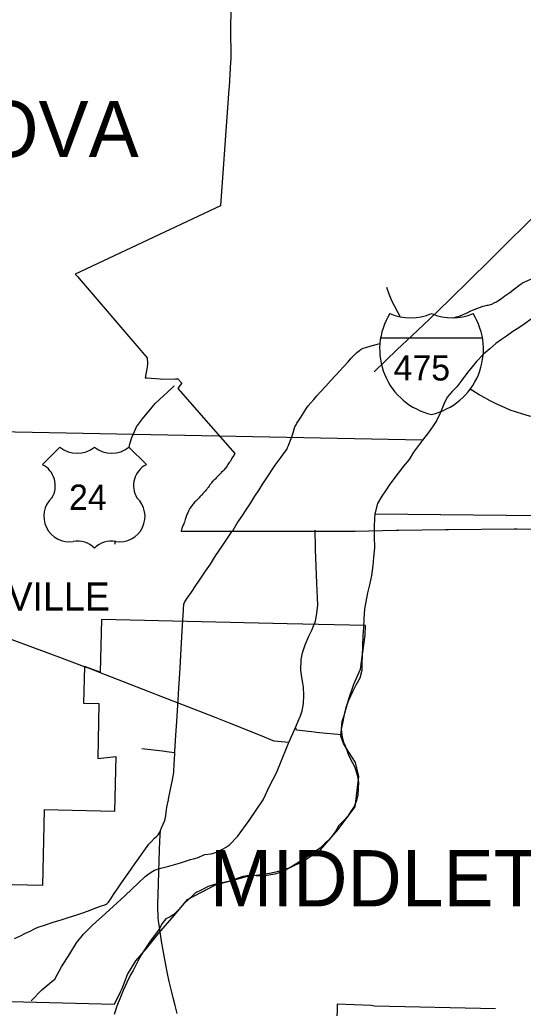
# Model space of a CAD drawing. Extents: x -232 to 448, y 619 to 1059.
# Drawn here: x 113.08 to 131.46, y 864.09 to 900.18 of the extents above; entities that cross this region are included whole.
import ezdxf

# ---------------------------------------------------------------- set-up
doc = ezdxf.new("R2010")
doc.units = 0
doc.layers.add('Default', color=7, linetype='Continuous')

msp = doc.modelspace()

# ---------------------------------------------------------------- linework, layer by layer
at = {"layer": 'Default'}
for p, q in [((126.25, 888.562), (129.971, 888.562)), ((114.542, 884.571), (113.908, 883.937)), ((114.542, 884.571), (113.908, 883.937)), ((117.698, 883.937), (117.063, 884.571)), ((117.698, 883.937), (117.063, 884.571)), ((116.063, 878.283), (116.016, 876.357)), ((115.437, 876.567), (115.405, 875.233)), ((115.405, 875.233), (115.969, 875.22)), ((115.969, 875.22), (115.921, 873.207)), ((116.583, 873.285), (116.535, 871.272)), ((113.97, 871.334), (113.904, 868.564)), ((116.535, 871.272), (113.97, 871.334)), ((113.904, 868.564), (111.904, 868.613)), ((112.16, 864.343), (116.541, 864.237))]:
    msp.add_line(p, q, dxfattribs=at)
for points in [[(120.796, 900.784), (120.793, 900.72), (120.769, 900.023), (120.77, 899.926), (120.779, 898.736), (120.774, 898.651), (120.716, 897.732), (120.711, 897.665), (120.406, 893.385)], [(129.536, 890.712), (129.559, 890.735), (130.184, 891.346), (130.828, 891.986), (131.61, 892.767), (132.138, 893.272), (132.641, 893.676), (132.77, 893.765)], [(120.406, 893.385), (115.098, 890.889)], [(127.784, 884.833), (111.649, 885.151), (111.657, 885.999), (110.121, 886.009), (110.165, 888.733), (104.807, 888.708), (99.321, 888.696), (99.344, 891.498)], [(131.422, 890.565), (131.436, 890.575), (131.52, 890.612), (131.739, 890.714), (131.945, 890.809), (132.197, 890.926), (132.43, 891.036), (132.65, 891.135), (132.869, 891.238), (132.922, 891.262)], [(115.098, 890.889), (115.191, 890.792), (115.242, 890.734), (117.5, 888.103), (117.558, 888.034), (117.723, 887.839), (117.73, 887.783), (117.742, 887.679), (117.739, 887.609), (117.734, 887.504), (117.721, 887.438), (117.657, 887.113)], [(127.389, 888.643), (128.034, 889.251), (128.765, 889.956), (129.536, 890.712)], [(130.822, 890.125), (130.964, 890.227), (131.136, 890.358), (131.293, 890.476), (131.386, 890.541), (131.422, 890.565)], [(126.971, 889.346), (126.897, 889.48), (126.768, 889.716), (126.664, 889.921), (126.563, 890.164), (126.476, 890.408)], [(130.518, 889.906), (130.574, 889.939), (130.665, 890.005), (130.792, 890.104), (130.822, 890.125)], [(128.905, 889.301), (128.951, 889.313), (129.077, 889.348), (129.151, 889.372), (129.239, 889.407), (129.355, 889.461), (129.435, 889.497), (129.505, 889.537), (129.586, 889.572), (129.73, 889.626), (129.899, 889.689), (129.985, 889.72), (130.061, 889.742), (130.148, 889.761), (130.173, 889.766)], [(130.173, 889.766), (130.23, 889.778), (130.31, 889.803), (130.401, 889.845), (130.485, 889.887), (130.518, 889.906)], [(132.003, 889.452), (131.763, 889.258), (131.532, 889.094), (131.294, 888.934), (131.075, 888.795), (130.843, 888.627), (130.67, 888.513), (130.463, 888.357), (130.235, 888.169), (130.011, 887.966), (129.749, 887.701), (129.589, 887.51), (129.421, 887.298), (129.214, 887.02), (129.029, 886.784), (128.863, 886.611), (128.698, 886.413), (128.589, 886.207), (128.441, 885.838), (128.292, 885.539), (128.169, 885.352), (128.006, 885.117), (127.784, 884.833)], [(126.016, 887.329), (126.854, 888.139), (127.389, 888.643)], [(120.835, 881.505), (120.865, 881.55), (121.017, 881.796), (121.186, 882.042), (121.346, 882.286), (121.512, 882.544), (121.663, 882.782), (121.812, 883.023), (121.929, 883.198), (122.047, 883.379), (122.175, 883.566), (122.301, 883.773), (122.351, 883.846), (122.399, 883.916), (122.473, 884.015), (122.617, 884.21), (122.738, 884.377), (122.824, 884.495), (122.858, 884.56), (122.894, 884.641), (122.937, 884.772), (122.988, 884.893), (123.024, 884.985), (123.057, 885.105), (123.098, 885.23), (123.124, 885.312), (123.166, 885.394), (123.198, 885.457), (123.252, 885.536), (123.323, 885.646), (123.449, 885.843), (123.55, 886.004), (123.605, 886.083), (123.699, 886.193), (123.811, 886.318), (123.922, 886.444), (124.055, 886.59), (124.249, 886.809), (124.43, 887.005), (124.603, 887.196), (124.757, 887.362), (124.894, 887.514), (125.063, 887.696), (125.178, 887.82), (125.294, 887.945), (125.386, 888.034), (125.475, 888.107), (125.541, 888.151), (125.615, 888.187), (125.712, 888.22), (125.901, 888.273), (126.144, 888.339), (126.224, 888.359)], [(117.657, 887.113), (117.716, 887.111), (118.201, 887.07), (118.271, 887.064), (118.761, 887.066), (118.842, 887.066), (118.982, 886.929), (118.996, 886.916), (118.925, 886.823), (118.842, 886.713), (120.05, 885.34), (120.923, 884.343)], [(117.072, 884.562), (117.1, 884.694), (117.173, 884.933), (117.267, 885.151), (117.334, 885.314), (117.552, 885.606), (117.91, 886.04), (118.015, 886.171), (118.629, 886.73), (118.714, 886.812)], [(129.893, 886.46), (129.856, 886.481), (129.617, 886.627), (129.519, 886.689)], [(133.976, 885.384), (133.832, 885.388), (133.533, 885.407), (133.249, 885.428), (133.012, 885.452), (132.773, 885.485), (132.549, 885.521), (132.322, 885.564), (132.13, 885.604), (131.914, 885.653), (131.694, 885.712), (131.449, 885.779), (131.219, 885.853), (130.987, 885.93), (130.802, 886.007), (130.601, 886.099), (130.422, 886.178), (130.247, 886.263), (130.053, 886.371), (129.893, 886.46)], [(127.784, 884.833), (127.454, 884.395), (127.289, 884.127), (127.091, 883.881), (126.894, 883.632), (126.589, 883.222), (126.433, 882.987), (126.297, 882.785), (126.142, 882.518), (126.046, 882.137)], [(120.923, 884.343), (120.893, 884.286), (120.876, 884.257), (120.859, 884.222), (120.821, 884.176), (120.793, 884.117), (120.765, 884.069), (120.722, 884.012), (120.698, 883.98), (120.673, 883.94), (120.646, 883.892), (120.617, 883.848), (120.592, 883.808), (120.566, 883.779), (120.536, 883.746), (120.494, 883.704), (120.445, 883.659), (120.429, 883.632), (120.391, 883.601), (120.361, 883.567), (120.342, 883.544), (120.307, 883.519), (120.276, 883.486), (120.246, 883.456), (120.219, 883.416), (120.199, 883.399), (120.165, 883.374), (120.144, 883.344), (120.102, 883.309), (120.082, 883.275), (120.063, 883.251), (120.034, 883.209), (120.005, 883.183), (119.986, 883.151), (119.964, 883.117), (119.935, 883.083), (119.915, 883.05), (119.883, 883.02), (119.843, 882.968)], [(119.843, 882.968), (119.794, 882.916), (119.764, 882.882), (119.749, 882.85), (119.723, 882.828), (119.687, 882.795), (119.647, 882.759), (119.632, 882.73), (119.605, 882.706), (119.558, 882.652), (119.532, 882.634), (119.503, 882.604), (119.472, 882.578), (119.424, 882.521), (119.38, 882.473), (119.361, 882.432), (119.336, 882.404), (119.3, 882.35), (119.265, 882.307), (119.25, 882.266), (119.236, 882.237), (119.207, 882.174), (119.189, 882.143), (119.179, 882.112), (119.152, 882.041), (119.14, 882.009), (119.131, 881.966), (119.119, 881.935), (119.106, 881.887), (119.088, 881.837), (119.075, 881.808), (119.062, 881.77), (119.048, 881.741), (119.033, 881.705), (119.009, 881.644), (118.995, 881.607), (118.982, 881.561), (118.971, 881.527), (118.967, 881.51)], [(126.046, 882.137), (126.025, 881.968), (126.019, 881.673), (126.011, 881.309), (126.024, 880.894), (125.994, 880.55), (125.972, 880.259), (125.914, 879.895), (125.84, 879.546), (125.771, 879.251), (125.716, 878.932), (125.668, 878.674), (125.643, 878.308), (125.631, 877.987), (125.601, 877.701), (125.594, 877.315), (125.582, 876.965), (125.572, 876.692), (125.565, 876.422), (125.494, 876.135), (125.347, 875.884), (125.223, 875.636), (125.076, 875.321), (124.987, 875.071), (124.92, 874.811), (124.865, 874.501), (124.811, 874.275), (124.842, 873.987)], [(126.046, 882.137), (144.042, 881.962), (143.608, 865.423), (159.393, 865.266)], [(118.743, 873.419), (118.744, 873.468), (118.755, 873.671), (118.779, 874.052), (118.812, 874.567), (118.84, 874.955), (118.865, 875.343), (118.888, 875.779), (118.91, 876.124), (118.927, 876.522), (118.955, 876.984), (118.978, 877.436), (119.005, 877.853), (119.032, 878.259), (119.052, 878.621), (119.054, 878.717), (119.061, 878.791), (119.072, 878.845), (119.094, 878.902), (119.127, 878.961), (119.192, 879.063), (119.345, 879.286), (119.503, 879.522), (119.641, 879.719), (119.859, 880.047), (120.035, 880.307), (120.228, 880.602), (120.465, 880.956), (120.662, 881.255), (120.835, 881.505)], [(118.967, 881.51), (120.959, 881.508), (123.62, 881.506), (123.642, 881.506), (123.727, 881.505), (125.217, 881.504), (125.226, 881.504), (125.325, 881.506), (126.816, 881.541), (126.865, 881.543), (126.922, 881.544), (128.625, 881.573), (128.649, 881.573), (128.731, 881.574), (131.127, 881.588), (131.15, 881.588), (131.233, 881.588), (132.031, 881.586), (132.058, 881.586), (132.137, 881.585), (133.955, 881.557)], [(123.88, 880.834), (123.877, 880.916), (123.862, 881.55)], [(116.561, 881.033), (116.558, 881.132)], [(123.801, 878.046), (123.825, 878.103), (123.871, 878.225), (123.916, 878.425), (123.955, 878.807), (123.925, 879.607), (123.88, 880.834)], [(115.438, 876.56), (114.537, 876.899), (111.009, 878.195), (107.105, 879.666), (106.119, 880.048)], [(125.697, 878.058), (122.838, 878.12), (116.063, 878.283)], [(123.311, 874.728), (123.387, 874.95), (123.442, 875.214), (123.453, 875.504), (123.442, 875.828), (123.397, 876.021), (123.339, 876.426), (123.353, 876.821), (123.399, 877.063), (123.498, 877.359), (123.633, 877.678), (123.694, 877.791), (123.749, 877.922), (123.801, 878.046)], [(124.801, 874.021), (124.85, 874.556), (124.927, 874.775), (125.095, 875.384), (125.279, 875.918), (125.514, 876.473), (125.688, 877.71), (125.697, 878.058)], [(116.016, 876.357), (115.437, 876.567)], [(115.987, 876.349), (115.658, 876.477), (115.438, 876.56)], [(118.084, 875.535), (118.024, 875.558), (115.987, 876.349)], [(119.432, 875.008), (118.084, 875.535)], [(120.73, 874.499), (120.191, 874.711), (119.432, 875.008)], [(122.841, 873.646), (122.902, 873.797), (123.149, 874.339), (123.184, 874.421), (123.308, 874.718), (123.311, 874.728)], [(122.371, 873.844), (122.328, 873.847), (121.927, 874.028), (120.73, 874.499)], [(123.897, 874.158), (123.841, 874.163), (123.179, 874.24), (123.172, 874.279), (123.149, 874.339)], [(124.842, 873.987), (124.899, 873.807), (124.956, 873.668), (125.023, 873.506), (125.072, 873.366), (125.131, 873.227), (125.231, 873.046), (125.294, 872.919), (125.353, 872.766), (125.409, 872.557), (125.447, 872.326), (125.437, 872.128), (125.42, 871.859), (125.363, 871.642), (125.283, 871.456), (125.15, 871.262), (125.051, 871.099), (124.898, 870.937), (124.73, 870.763), (124.62, 870.568), (124.492, 870.393), (124.363, 870.23), (124.219, 870.101), (124.041, 869.937), (123.833, 869.793), (123.559, 869.608), (123.349, 869.476), (123.136, 869.338), (122.912, 869.2), (122.733, 869.106), (122.543, 869.033), (122.384, 868.988), (122.025, 868.925), (121.706, 868.924), (121.464, 868.934), (121.218, 868.897), (121.011, 868.821), (120.751, 868.731), (120.524, 868.679), (120.233, 868.622), (119.956, 868.534), (119.696, 868.403), (119.493, 868.3), (119.311, 868.115), (119.127, 867.962), (119.003, 867.822), (118.865, 867.664), (118.702, 867.508), (118.573, 867.424), (118.409, 867.355), (118.279, 867.178), (118.17, 866.98), (118.069, 866.844), (117.943, 866.678), (117.785, 866.466), (117.627, 866.226), (117.527, 866.055), (117.387, 865.802), (117.216, 865.469), (117.121, 865.306), (116.991, 865.025), (116.848, 864.733), (116.751, 864.498), (116.626, 864.16), (116.52, 863.864)], [(122.902, 873.797), (122.371, 873.844)], [(124.282, 874.122), (123.897, 874.158)], [(124.833, 874.071), (124.282, 874.122)], [(125.326, 871.443), (125.459, 872.544), (125.329, 873.057), (125.001, 873.567), (124.892, 873.752), (124.801, 874.021)], [(118.743, 873.419), (118.532, 873.441), (118.292, 873.47), (117.532, 873.554)], [(122.638, 873.14), (122.841, 873.646)], [(115.921, 873.207), (116.583, 873.285)], [(118.509, 871.722), (118.569, 872.03), (118.648, 872.43), (118.697, 872.696), (118.707, 872.797), (118.714, 872.945), (118.731, 873.239), (118.736, 873.316)], [(118.736, 873.316), (118.743, 873.419)], [(119.425, 869.548), (119.554, 869.576), (119.828, 869.701), (120.065, 869.731), (120.262, 869.791), (120.501, 869.905), (120.589, 869.958), (120.731, 870.06), (121.03, 870.354), (121.454, 870.942), (121.965, 871.702), (122.207, 872.216), (122.456, 872.686), (122.638, 873.14)], [(118.209, 870.573), (118.254, 870.677), (118.314, 870.815), (118.37, 870.942), (118.389, 871.005), (118.405, 871.116), (118.416, 871.248), (118.428, 871.332), (118.448, 871.434), (118.504, 871.696), (118.509, 871.722)], [(121.354, 868.902), (121.799, 868.954), (122.194, 869.022), (122.532, 869.098), (122.953, 869.227), (123.422, 869.463), (124.053, 869.874), (124.7, 870.615), (125.326, 871.443)], [(112.889, 866.63), (113.102, 866.735), (113.289, 866.824), (113.454, 866.906), (113.593, 866.98), (113.665, 867.013), (113.754, 867.045), (114.012, 867.133), (114.299, 867.225), (114.588, 867.322), (114.848, 867.404), (115.124, 867.49), (115.339, 867.564), (115.582, 867.643), (115.795, 867.725), (116.03, 867.812), (116.183, 867.865), (116.226, 867.886), (116.27, 867.912), (116.314, 867.961), (116.396, 868.085), (116.526, 868.282), (116.64, 868.449), (116.762, 868.632), (116.874, 868.794), (116.994, 868.961), (117.139, 869.162), (117.273, 869.357), (117.433, 869.585), (117.601, 869.822), (117.73, 869.999), (117.793, 870.084), (117.866, 870.153), (118.001, 870.292)], [(118.001, 870.292), (118.085, 870.373), (118.125, 870.418), (118.167, 870.485), (118.209, 870.573)], [(118.824, 863.89), (118.747, 864.186), (118.676, 864.464), (118.611, 864.729), (118.576, 864.869), (118.537, 865.065), (118.474, 865.362), (118.41, 865.676), (118.348, 866.004), (118.299, 866.264), (118.265, 866.462), (118.218, 866.798), (118.17, 867.134), (118.146, 867.282), (118.13, 867.406), (118.124, 867.513), (118.119, 867.71), (118.116, 867.893), (118.128, 868.251), (118.139, 868.625), (118.155, 869.083), (118.166, 869.475), (118.183, 869.87), (118.196, 870.184), (118.2, 870.406)], [(118.2, 870.406), (118.2, 870.416), (118.209, 870.573)], [(113.496, 864.358), (113.504, 864.365), (113.876, 864.758), (114.245, 865.068), (114.36, 865.148), (114.596, 865.597), (114.9, 866.072), (115.144, 866.478), (115.4, 866.792), (115.73, 867.124), (116.202, 867.548), (116.927, 868.201), (117.404, 868.652), (117.65, 868.895), (117.754, 868.971), (117.873, 869.053), (118, 869.126), (118.222, 869.202), (118.518, 869.272), (118.944, 869.4), (119.312, 869.523), (119.425, 869.548)], [(116.541, 864.237), (116.756, 864.685), (116.811, 864.806), (117.007, 865.315), (117.311, 865.815), (117.703, 866.272), (118.144, 866.817), (118.728, 867.489), (119.197, 868.061), (120.242, 868.61), (120.777, 868.734), (121.354, 868.902)], [(130.451, 864.065), (126.027, 864.164), (125.908, 864.193), (124.664, 864.242), (124.619, 861.454), (123.239, 861.478)]]:
    msp.add_lwpolyline(points, dxfattribs=at)
for centre, radius, start, end in [((128.661, 888.153), 2.445, 147.8216, 256.9941), ((128.661, 888.153), 2.445, 147.8216, 256.9941), ((127.351, 891.252), 1.951, 247.0848, 292.9105), ((127.351, 891.252), 1.951, 247.0848, 292.9105), ((127.56, 888.153), 2.445, 283.0065, 32.1787), ((128.87, 891.252), 1.951, 247.0916, 292.9084), ((127.56, 888.153), 2.445, 283.0065, 32.1787), ((128.87, 891.252), 1.951, 247.0916, 292.9084), ((115.173, 885.372), 1.019, 231.813, 308.187), ((115.173, 885.372), 1.019, 231.813, 308.187), ((116.433, 885.372), 1.019, 231.813, 308.187), ((116.433, 885.372), 1.019, 231.813, 308.187), ((113.512, 883.171), 0.862, 329.1175, 62.6108), ((113.512, 883.171), 0.862, 329.1175, 62.6108), ((118.094, 883.171), 0.862, 117.3892, 210.8825), ((118.094, 883.171), 0.862, 117.3892, 210.8825), ((114.886, 882.049), 0.93, 133.0046, 278.7282), ((114.886, 882.049), 0.93, 133.0046, 278.7282), ((116.72, 882.049), 0.93, 261.2718, 46.9954), ((116.72, 882.049), 0.93, 261.2718, 46.9954), ((115.199, 880.315), 0.832, 43.4177, 101.8742), ((115.199, 880.315), 0.832, 43.4177, 101.8742), ((116.425, 880.259), 0.883, 79.9613, 134.7468), ((116.425, 880.259), 0.883, 79.9613, 134.7468)]:
    msp.add_arc(centre, radius, start, end, dxfattribs=at)

# ---------------------------------------------------------------- texts
for s, height, p in [('MONCLOVA', 2.052, (101.717, 895.168)), ('475', 0.9234, (126.727, 887.01)), ('24', 0.9234, (114.876, 882.287)), ('WATERVILLE', 1.026, (107.673, 878.609)), ('MIDDLETON', 2.052, (120.012, 867.809))]:
    msp.add_text(s, height=height, dxfattribs=at).set_placement(p)

doc.saveas('drawing.dxf')
